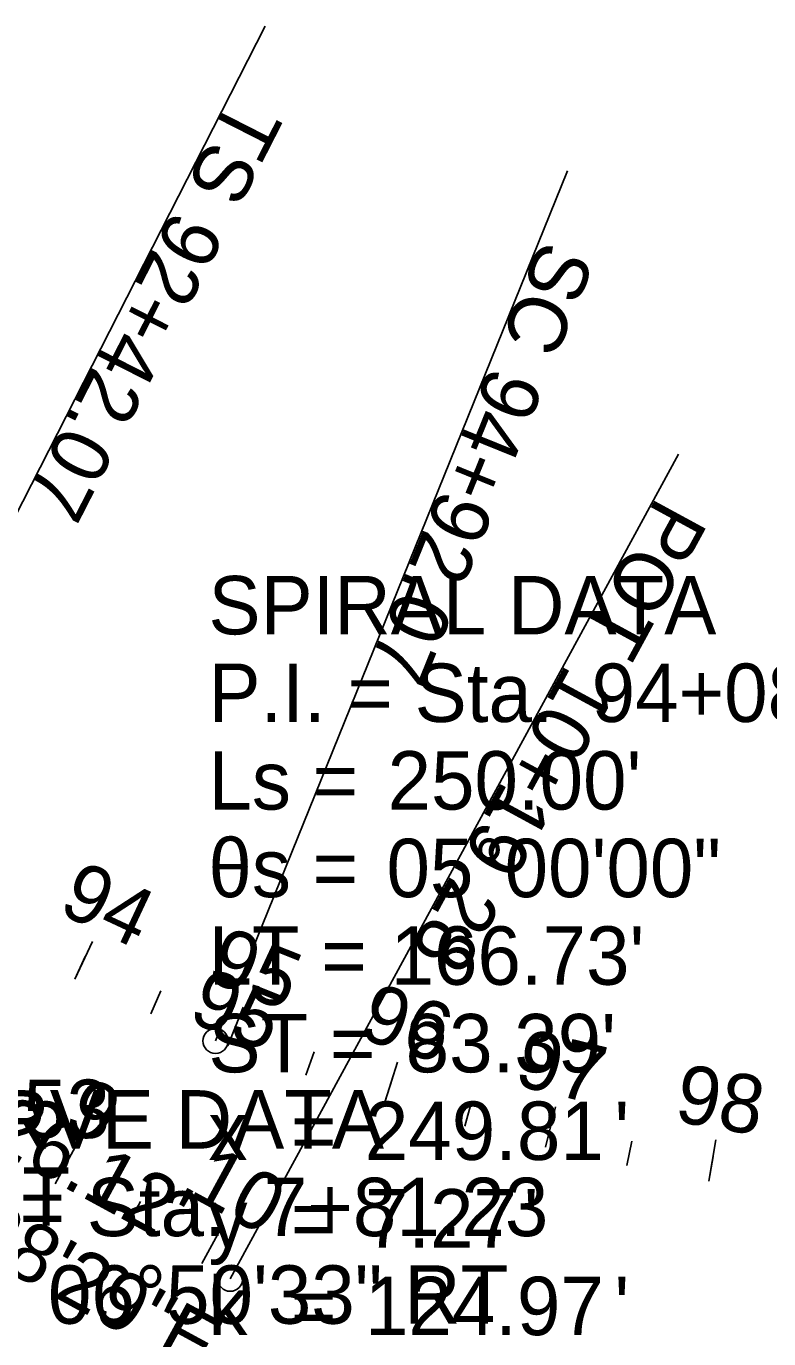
# Model space of a CAD drawing. Extents: x 2000474 to 2003418, y 251807 to 253801.
# Drawn here: x 2001988 to 2002433, y 252692 to 253479 of the extents above; entities that cross this region are included whole.
import ezdxf

# ---------------------------------------------------------------- set-up
doc = ezdxf.new("R2010")
doc.units = 0
for name, color, linetype in [('BD_X_Building', 7, 'Continuous'), ('DR_X_Flow_Arrow', 7, 'Continuous'), ('DV_X_Lot_Line', 7, 'Continuous'), ('DV_X_Property_Line', 7, 'Continuous'), ('DV_X_Township_Line', 7, 'Continuous'), ('GE_P_Alignment_100_Stations', 7, 'Continuous'), ('RW_P_Text', 7, 'Continuous'), ('RW_X_CL_100_Stations', 7, 'Continuous'), ('RW_X_CL_500_Stations', 7, 'Continuous'), ('SC_Scratch3', 7, 'Continuous'), ('SC_Scratch5', 7, 'Continuous'), ('SC_Shading1', 7, 'Continuous'), ('TX_X_50', 7, 'Continuous')]:
    doc.layers.add(name, color=color, linetype=linetype)

msp = doc.modelspace()

# ---------------------------------------------------------------- linework, layer by layer
at = {"layer": 'DR_X_Flow_Arrow'}
for p, q in [((2002110.5, 252728.04), (2002379.12, 253222.25)), ((2002005.7, 252785), (2002017.64, 252806.96)), ((2002049.63, 252761.12), (2002056.79, 252774.3)), ((2002093.56, 252737.24), (2002105.5, 252759.21))]:
    msp.add_line(p, q, dxfattribs=at)
msp.add_circle((2002110.5, 252728.04), 7.5, dxfattribs=at)
at = {"layer": 'DV_X_Lot_Line'}
for p, q in [((2002005.7, 252785), (2002012.86, 252798.18)), ((2002093.56, 252737.24), (2002105.5, 252759.21))]:
    msp.add_line(p, q, dxfattribs=at)
at = {"layer": 'DV_X_Property_Line'}
for p, q in [((2002017.36, 252907.52), (2002023.7, 252921.11)), ((2002109.05, 252867.65), (2002118.3, 252890.88)), ((2002203.18, 252833.94), (2002207.74, 252848.23)), ((2002299.42, 252806.88), (2002302.98, 252821.45)), ((2002397.32, 252786.6), (2002399.85, 252801.38))]:
    msp.add_line(p, q, dxfattribs=at)
at = {"layer": 'RW_P_Text'}
for p, q in [((2002110.5, 252728.04), (2002379.12, 253222.25)), ((2002093.56, 252737.24), (2002105.5, 252759.21))]:
    msp.add_line(p, q, dxfattribs=at)
msp.add_circle((2002110.5, 252728.04), 7.5, dxfattribs=at)
at = {"layer": 'RW_X_CL_100_Stations'}
for p, q in [((2001875.85, 252977.63), (2002131.41, 253478.72)), ((2002101.69, 252870.61), (2002312.6, 253392.07)), ((2002110.5, 252728.04), (2002379.12, 253222.25))]:
    msp.add_line(p, q, dxfattribs=at)
for centre in [(2002101.69, 252870.61), (2002110.5, 252728.04)]:
    msp.add_circle(centre, 7.5, dxfattribs=at)
at = {"layer": 'SC_Scratch3'}
for p, q in [((2001875.85, 252977.63), (2002131.41, 253478.72)), ((2002101.69, 252870.61), (2002312.6, 253392.07)), ((2002109.05, 252867.65), (2002114.6, 252881.59))]:
    msp.add_line(p, q, dxfattribs=at)
msp.add_circle((2002101.69, 252870.61), 7.5, dxfattribs=at)
at = {"layer": 'TX_X_50'}
for p, q in [((2001875.85, 252977.63), (2002131.41, 253478.72)), ((2002101.69, 252870.61), (2002312.6, 253392.07)), ((2002017.36, 252907.52), (2002027.93, 252930.17)), ((2002062.91, 252886.92), (2002068.91, 252900.67)), ((2002109.05, 252867.65), (2002118.3, 252890.88)), ((2002155.82, 252849.98), (2002160.88, 252864.1)), ((2002203.18, 252833.94), (2002210.78, 252857.76)), ((2002251.06, 252819.57), (2002255.12, 252834.01)), ((2002299.42, 252806.88), (2002305.35, 252831.17)), ((2002348.2, 252795.89), (2002351.24, 252810.57)), ((2002397.32, 252786.6), (2002401.54, 252811.24))]:
    msp.add_line(p, q, dxfattribs=at)
msp.add_circle((2002101.69, 252870.61), 7.5, dxfattribs=at)

# ---------------------------------------------------------------- texts
at = {"layer": 'BD_X_Building'}
for s, p in [("226.12'", (2001940.21, 252821.26)), ('S61°28\'29"E', (2001860.9, 252795.41))]:
    msp.add_text(s, height=35, rotation=331.47468, dxfattribs=at).set_placement(p)
for s, p in [('5+10.53', (2001868.05, 252812.4)), ('CURVE DATA', (2001901.02, 252806.08)), ('42°15\'01" RT', (2001738.72, 252759.9)), ('P.I. = Sta. ', (2001901.02, 252753.58)), ('7+81.23', (2002130.63, 252753.58)), ('06°50\'33" RT', (2002001.3, 252701.08))]:
    msp.add_text(s, height=35, dxfattribs=at).set_placement(p)
at = {"layer": 'DR_X_Flow_Arrow'}
for s, rotation, p in [('POT', 241.47468, (2002366.44, 253197.7)), ('10+19.28', 241.47468, (2002311.94, 253097.43)), ('9', 331.47468, (2002009.07, 252819.4)), ('10', 331.47468, (2002084.68, 252778.31))]:
    msp.add_text(s, height=35, rotation=rotation, dxfattribs=at).set_placement(p)
at = {"layer": 'DV_X_Lot_Line'}
msp.add_text('10', height=35, rotation=331.47468, dxfattribs=at).set_placement((2002084.68, 252778.31))
at = {"layer": 'DV_X_Property_Line'}
msp.add_text('95', height=35, rotation=338.29546, dxfattribs=at).set_placement((2002084.3, 252882.77))
at = {"layer": 'DV_X_Township_Line'}
for s, p in [("226.12'", (2001940.21, 252821.26)), ('S61°28\'29"E', (2001860.9, 252795.41))]:
    msp.add_text(s, height=35, rotation=331.47468, dxfattribs=at).set_placement(p)
for s, p in [('5+10.53', (2001868.05, 252812.4)), ('CURVE DATA', (2001901.02, 252806.08)), ('42°15\'01" RT', (2001738.72, 252759.9)), ('P.I. = Sta. ', (2001901.02, 252753.58)), ('7+81.23', (2002130.63, 252753.58)), ('06°50\'33" RT', (2002001.3, 252701.08))]:
    msp.add_text(s, height=35, dxfattribs=at).set_placement(p)
at = {"layer": 'GE_P_Alignment_100_Stations'}
for s, p in [("226.12'", (2001940.21, 252821.26)), ('S61°28\'29"E', (2001860.9, 252795.41))]:
    msp.add_text(s, height=35, rotation=331.47468, dxfattribs=at).set_placement(p)
for s, p in [('5+10.53', (2001868.05, 252812.4)), ('CURVE DATA', (2001901.02, 252806.08)), ('42°15\'01" RT', (2001738.72, 252759.9)), ('P.I. = Sta. ', (2001901.02, 252753.58)), ('7+81.23', (2002130.63, 252753.58)), ('06°50\'33" RT', (2002001.3, 252701.08))]:
    msp.add_text(s, height=35, dxfattribs=at).set_placement(p)
at = {"layer": 'RW_P_Text'}
for s, rotation, p in [('POT', 241.47468, (2002366.44, 253197.7)), ('10+19.28', 241.47468, (2002311.94, 253097.43)), ('10', 331.47468, (2002084.68, 252778.31))]:
    msp.add_text(s, height=35, rotation=rotation, dxfattribs=at).set_placement(p)
at = {"layer": 'RW_X_CL_100_Stations'}
for s, rotation, p in [('TS', 242.97809, (2002111.08, 253437.58)), ('92+42.07', 242.97809, (2002076.52, 253369.8)), ('SC', 247.97811, (2002296.96, 253351.83)), ('94+92.07', 247.97811, (2002266.39, 253276.26)), ('POT', 241.47468, (2002366.44, 253197.7)), ('10+19.28', 241.47468, (2002311.94, 253097.43))]:
    msp.add_text(s, height=35, rotation=rotation, dxfattribs=at).set_placement(p)
at = {"layer": 'RW_X_CL_500_Stations'}
for s, p in [('SPIRAL DATA', (2002097.47, 253114.25)), ('P.I. = Sta. ', (2002097.47, 253061.75)), ('94+08.80', (2002327.07, 253061.75)), ("250.00'", (2002204.81, 253009.25)), ('Ls = ', (2002097.47, 253009.25)), ('θs = ', (2002097.47, 252956.75)), ('05°00\'00"', (2002204.15, 252956.75)), ('LT = ', (2002097.47, 252904.25)), ("166.73'", (2002206.6, 252904.25)), ('ST = ', (2002097.47, 252851.75)), ("83.39'", (2002215.67, 252851.75)), ('249.81', (2002191.21, 252799.25)), ("'", (2002340.7, 252799.25)), ('x  = ', (2002097.47, 252799.25)), ('7.27', (2002191.21, 252746.75)), ("'", (2002286.34, 252746.75)), ('y  = ', (2002097.47, 252746.75)), ('k  = ', (2002097.47, 252694.25)), ('124.97', (2002191.21, 252694.25)), ("'", (2002340.7, 252694.25))]:
    msp.add_text(s, height=35, dxfattribs=at).set_placement(p)
at = {"layer": 'SC_Scratch3'}
for s, rotation, p in [('TS', 242.97809, (2002111.08, 253437.58)), ('92+42.07', 242.97809, (2002076.52, 253369.8)), ('SC', 247.97811, (2002296.96, 253351.83)), ('94+92.07', 247.97811, (2002266.39, 253276.26))]:
    msp.add_text(s, height=35, rotation=rotation, dxfattribs=at).set_placement(p)
at = {"layer": 'SC_Scratch5'}
for s, p in [('SPIRAL DATA', (2002097.47, 253114.25)), ('P.I. = Sta. ', (2002097.47, 253061.75)), ('94+08.80', (2002327.07, 253061.75)), ("250.00'", (2002204.81, 253009.25)), ('Ls = ', (2002097.47, 253009.25)), ('θs = ', (2002097.47, 252956.75)), ('05°00\'00"', (2002204.15, 252956.75)), ('LT = ', (2002097.47, 252904.25)), ("166.73'", (2002206.6, 252904.25)), ('ST = ', (2002097.47, 252851.75)), ("83.39'", (2002215.67, 252851.75)), ('249.81', (2002191.21, 252799.25)), ("'", (2002340.7, 252799.25)), ('x  = ', (2002097.47, 252799.25)), ('7.27', (2002191.21, 252746.75)), ("'", (2002286.34, 252746.75)), ('y  = ', (2002097.47, 252746.75)), ('k  = ', (2002097.47, 252694.25)), ('124.97', (2002191.21, 252694.25)), ("'", (2002340.7, 252694.25))]:
    msp.add_text(s, height=35, dxfattribs=at).set_placement(p)
at = {"layer": 'SC_Shading1'}
for s, p in [('SPIRAL DATA', (2002097.47, 253114.25)), ('P.I. = Sta. ', (2002097.47, 253061.75)), ('94+08.80', (2002327.07, 253061.75)), ("250.00'", (2002204.81, 253009.25)), ('Ls = ', (2002097.47, 253009.25)), ('θs = ', (2002097.47, 252956.75)), ('05°00\'00"', (2002204.15, 252956.75)), ('LT = ', (2002097.47, 252904.25)), ("166.73'", (2002206.6, 252904.25)), ('ST = ', (2002097.47, 252851.75)), ("83.39'", (2002215.67, 252851.75)), ('249.81', (2002191.21, 252799.25)), ("'", (2002340.7, 252799.25)), ('x  = ', (2002097.47, 252799.25)), ('7.27', (2002191.21, 252746.75)), ("'", (2002286.34, 252746.75)), ('y  = ', (2002097.47, 252746.75)), ('k  = ', (2002097.47, 252694.25)), ('124.97', (2002191.21, 252694.25)), ("'", (2002340.7, 252694.25))]:
    msp.add_text(s, height=35, dxfattribs=at).set_placement(p)
at = {"layer": 'TX_X_50'}
for s, rotation, p in [('TS', 242.97809, (2002111.08, 253437.58)), ('92+42.07', 242.97809, (2002076.52, 253369.8)), ('SC', 247.97811, (2002296.96, 253351.83)), ('94+92.07', 247.97811, (2002266.39, 253276.26)), ('94', 334.97354, (2002006.46, 252947.74)), ('95', 338.29546, (2002095.2, 252907.43)), ('96', 342.29547, (2002186.7, 252872.62)), ('97', 346.29548, (2002279.62, 252844.48)), ('98', 350.2955, (2002375.7, 252822.6))]:
    msp.add_text(s, height=35, rotation=rotation, dxfattribs=at).set_placement(p)

doc.saveas('drawing.dxf')
